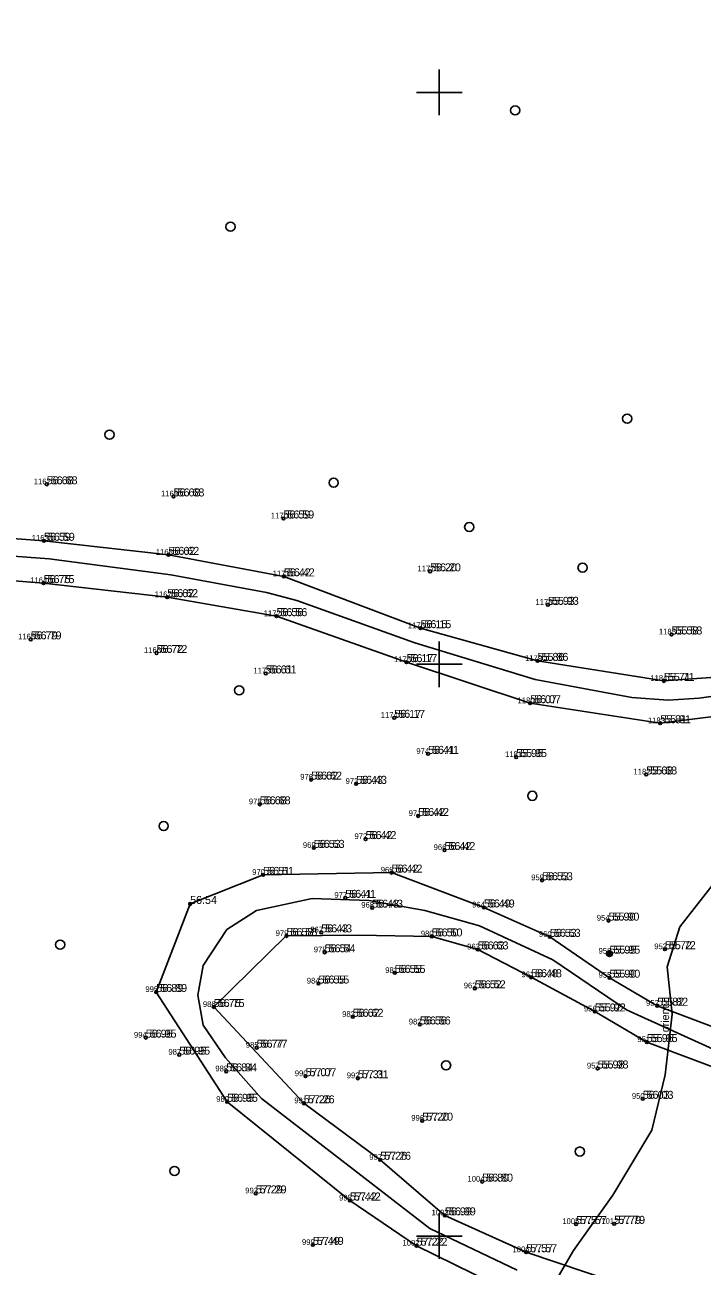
# Model space of a CAD drawing. Extents: x 554846 to 556995, y 6445875 to 6446723.
# Drawn here: x 555263.8 to 555323, y 6446097.4 to 6446205.9 of the extents above; entities that cross this region are included whole.
import ezdxf

# ---------------------------------------------------------------- set-up
doc = ezdxf.new("R2010")
doc.units = 0
for name, color, linetype in [('HALJASTUS', 7, 'Continuous'), ('KORGUS-EH2000', 7, 'Continuous'), ('MOOTKORG-EH2000', 7, 'Continuous'), ('MOOTMPUNKT', 7, 'Continuous'), ('MOOTNR', 7, 'Continuous'), ('RAJATIS', 7, 'Continuous'), ('SITRASS', 7, 'Continuous'), ('TEE', 7, 'Continuous'), ('VORK', 7, 'Continuous')]:
    doc.layers.add(name, color=color, linetype=linetype)

msp = doc.modelspace()

# ---------------------------------------------------------------- linework, layer by layer
at = {"layer": 'HALJASTUS'}
for centre in [(555306.63, 6446198.42), (555281.76, 6446188.25), (555316.42, 6446171.47), (555271.19, 6446170.07), (555290.78, 6446165.87), (555302.62, 6446161.99), (555312.52, 6446158.44), (555282.52, 6446147.72), (555308.14, 6446138.49), (555275.92, 6446135.85), (555266.88, 6446125.48), (555300.6, 6446114.93), (555312.28, 6446107.39), (555276.87, 6446105.69)]:
    msp.add_circle(centre, 0.4, dxfattribs=at)
at = {"layer": 'KORGUS-EH2000'}
for centre in [(555265.71, 6446165.73), (555276.79, 6446164.67), (555286.39, 6446162.74), (555265.47, 6446160.79), (555276.34, 6446159.56), (555286.43, 6446157.68), (555299.2, 6446158.12), (555265.44, 6446157.09), (555276.24, 6446155.86), (555309.5, 6446155.19), (555285.78, 6446154.2), (555298.36, 6446153.15), (555264.31, 6446152.17), (555320.29, 6446152.6), (555275.3, 6446150.98), (555297.14, 6446150.18), (555308.59, 6446150.29), (555284.84, 6446149.19), (555319.62, 6446148.54), (555307.94, 6446146.59), (555296.07, 6446145.31), (555319.3, 6446144.84), (555299.02, 6446142.16), (555306.72, 6446141.88), (555288.81, 6446139.91), (555318.09, 6446140.36), (555292.74, 6446139.54), (555284.32, 6446137.75), (555298.16, 6446136.73), (555293.57, 6446134.71), (555289.04, 6446133.94), (555300.46, 6446133.75), (555284.61, 6446131.58), (555295.84, 6446131.78), (555308.98, 6446131.11), (555291.79, 6446129.57), (555294.14, 6446128.71), (555303.9, 6446128.73), (555314.79, 6446127.58), (555286.66, 6446126.24), (555289.69, 6446126.55), (555299.34, 6446126.2), (555309.66, 6446126.16), (555289.99, 6446124.81), (555303.36, 6446125.06), (555319.72, 6446125.08), (555314.87, 6446124.69), (555296.11, 6446123.01), (555308.02, 6446122.63), (555314.87, 6446122.59), (555289.45, 6446122.08), (555303.11, 6446121.66), (555275.28, 6446121.34), (555280.3, 6446120.03), (555313.59, 6446119.64), (555319.05, 6446120.14), (555292.44, 6446119.17), (555298.31, 6446118.5), (555274.36, 6446117.35), (555284.05, 6446116.47), (555318.13, 6446116.96), (555277.29, 6446115.86), (555281.39, 6446114.4), (555288.32, 6446113.98), (555313.84, 6446114.65), (555292.89, 6446113.8), (555281.47, 6446111.74), (555317.78, 6446112), (555288.17, 6446111.61), (555298.51, 6446110.09), (555294.84, 6446106.67), (555303.75, 6446104.76), (555283.97, 6446103.73), (555292.2, 6446103.11), (555300.5, 6446101.81), (555311.95, 6446101.05), (555315.29, 6446101.07), (555288.96, 6446099.23), (555298.02, 6446099.16), (555307.6, 6446098.59)]:
    msp.add_circle(centre, 0.125, dxfattribs=at)
at = {"layer": 'MOOTMPUNKT'}
for centre in [(555265.71, 6446165.73), (555276.79, 6446164.67), (555286.39, 6446162.74), (555265.47, 6446160.79), (555276.34, 6446159.56), (555286.43, 6446157.68), (555299.2, 6446158.12), (555265.44, 6446157.09), (555276.24, 6446155.86), (555309.5, 6446155.19), (555285.78, 6446154.2), (555298.36, 6446153.15), (555264.31, 6446152.17), (555320.29, 6446152.6), (555275.3, 6446150.98), (555297.14, 6446150.18), (555308.59, 6446150.29), (555284.84, 6446149.19), (555319.62, 6446148.54), (555307.94, 6446146.59), (555296.07, 6446145.31), (555319.3, 6446144.84), (555299.02, 6446142.16), (555306.72, 6446141.88), (555288.81, 6446139.91), (555318.09, 6446140.36), (555292.74, 6446139.54), (555284.32, 6446137.75), (555298.16, 6446136.73), (555293.57, 6446134.71), (555289.04, 6446133.94), (555300.46, 6446133.75), (555284.61, 6446131.58), (555295.84, 6446131.78), (555308.98, 6446131.11), (555291.79, 6446129.57), (555278.24, 6446129.04), (555294.14, 6446128.71), (555303.9, 6446128.73), (555314.79, 6446127.58), (555286.66, 6446126.24), (555289.69, 6446126.55), (555299.34, 6446126.2), (555309.66, 6446126.16), (555289.99, 6446124.81), (555303.36, 6446125.06), (555319.72, 6446125.08), (555314.87, 6446124.69), (555296.11, 6446123.01), (555308.02, 6446122.63), (555314.87, 6446122.59), (555289.45, 6446122.08), (555303.11, 6446121.66), (555275.28, 6446121.34), (555280.3, 6446120.03), (555313.59, 6446119.64), (555319.05, 6446120.14), (555292.44, 6446119.17), (555298.31, 6446118.5), (555274.36, 6446117.35), (555284.05, 6446116.47), (555318.13, 6446116.96), (555277.29, 6446115.86), (555281.39, 6446114.4), (555288.32, 6446113.98), (555313.84, 6446114.65), (555292.89, 6446113.8), (555281.47, 6446111.74), (555317.78, 6446112), (555288.17, 6446111.61), (555298.51, 6446110.09), (555294.84, 6446106.67), (555303.75, 6446104.76), (555283.97, 6446103.73), (555292.2, 6446103.11), (555300.5, 6446101.81), (555311.95, 6446101.05), (555315.29, 6446101.07), (555288.96, 6446099.23), (555298.02, 6446099.16), (555307.6, 6446098.59)]:
    msp.add_circle(centre, 0.125, dxfattribs=at)
at = {"layer": 'RAJATIS'}
for radius in [0.25, 0.0234]:
    msp.add_circle((555314.87, 6446124.69), radius, dxfattribs=at)
at = {"layer": 'SITRASS'}
msp.add_lwpolyline([(555305.76, 6446088.51), (555311.73, 6446098.73), (555315.17, 6446103.59), (555318.56, 6446109.25), (555319.73, 6446114.11), (555320.34, 6446119.41), (555319.91, 6446123.53), (555321.02, 6446127.04), (555334.92, 6446144.83), (555339.43, 6446148.13), (555341.89, 6446149.32), (555360.14, 6446155.97), (555367.8, 6446158.19), (555388.11, 6446164.69), (555397.64, 6446165.99), (555410.43, 6446167.47), (555421.22, 6446169.41), (555430.68, 6446171.97), (555436.58, 6446173.1), (555447.3, 6446175.1), (555466.49, 6446179.22), (555474.82, 6446180.34)], dxfattribs=at)
at = {"layer": 'TEE'}
for points in [[(555247.52, 6446162.12), (555265.47, 6446160.79), (555276.34, 6446159.56), (555286.43, 6446157.68), (555298.36, 6446153.15), (555308.59, 6446150.29), (555319.62, 6446148.54), (555327.84, 6446149.13), (555331.85, 6446150.36), (555334.58, 6446153.35), (555334.79, 6446162.55), (555336.04, 6446172.56), (555338.65, 6446179.44), (555343.2, 6446186.87), (555348.65, 6446195.75), (555359.36, 6446208.2), (555362, 6446212.55), (555362.39, 6446223.83), (555370.17, 6446230.71), (555377.98, 6446233.66), (555385.78, 6446233.47)], [(555385.54, 6446229.68), (555377.59, 6446229.89), (555371.94, 6446227.34), (555367.7, 6446222.17), (555366.29, 6446212.41), (555362.23, 6446206.74), (555351.69, 6446194.25), (555346.07, 6446185.37), (555342.02, 6446178.62), (555340, 6446174.09), (555338.06, 6446163.9), (555338.78, 6446155.44), (555337.33, 6446148.82), (555334.66, 6446147.05), (555328.59, 6446146.01), (555319.3, 6446144.84), (555307.94, 6446146.59), (555297.14, 6446150.18), (555285.78, 6446154.2), (555276.24, 6446155.86), (555265.44, 6446157.09), (555246.52, 6446158.61)], [(555361.12, 6446207.96), (555350.96, 6446195.96), (555349.72, 6446194.5), (555348.27, 6446191.98), (555340.58, 6446179.38), (555338.43, 6446174.33), (555337.37, 6446169.52), (555336.62, 6446164.08), (555336.56, 6446160.5), (555336.73, 6446155.21), (555336.17, 6446151.94), (555334.85, 6446149.89), (555332.77, 6446148.62), (555329.39, 6446147.99), (555322.71, 6446147.02), (555320, 6446146.87), (555316.83, 6446147.08), (555308.37, 6446148.65), (555297.88, 6446151.87), (555287.56, 6446155.58), (555284.9, 6446156.28), (555276.56, 6446157.82), (555265.92, 6446159.2), (555247.57, 6446160.59)], [(555306.24, 6446095.09), (555298.02, 6446099.16), (555292.2, 6446103.11), (555281.47, 6446111.74), (555275.28, 6446121.34), (555278.24, 6446129.04), (555284.61, 6446131.58), (555295.84, 6446131.78), (555303.9, 6446128.73), (555309.66, 6446126.16), (555314.87, 6446122.59), (555319.05, 6446120.14), (555327.6, 6446116.89)], [(555306.81, 6446097.03), (555299.18, 6446100.65), (555292.5, 6446105.81), (555284.46, 6446112.02), (555281.34, 6446115.58), (555279.38, 6446118.44), (555278.91, 6446121.05), (555279.37, 6446123.66), (555281.44, 6446126.8), (555284.05, 6446128.47), (555288.9, 6446129.52), (555293.85, 6446129.35), (555298.74, 6446128.48), (555303.51, 6446127.13), (555309.92, 6446124.16), (555316.36, 6446119.78), (555323.93, 6446116.33)], [(555326.11, 6446113.96), (555318.13, 6446116.96), (555313.59, 6446119.64), (555308.02, 6446122.63), (555303.36, 6446125.06), (555299.34, 6446126.2), (555292.93, 6446126.32), (555286.64, 6446126.24), (555280.3, 6446120.03), (555288.17, 6446111.61), (555294.84, 6446106.67), (555300.5, 6446101.81), (555307.6, 6446098.59), (555315.46, 6446095.94)]]:
    msp.add_lwpolyline(points, dxfattribs=at)
at = {"layer": 'VORK'}
for p, q in [((555300, 6446202), (555300, 6446198)), ((555298, 6446200), (555302, 6446200)), ((555300, 6446152), (555300, 6446148)), ((555298, 6446150), (555302, 6446150)), ((555300, 6446102), (555300, 6446098)), ((555298, 6446100), (555302, 6446100))]:
    msp.add_line(p, q, dxfattribs=at)

# ---------------------------------------------------------------- texts
at = {"layer": 'KORGUS-EH2000'}
for s, p in [('56.68', (555266.06, 6446165.73)), ('56.68', (555277.14, 6446164.67)), ('56.59', (555286.73, 6446162.74)), ('56.59', (555265.82, 6446160.79)), ('56.62', (555276.69, 6446159.56)), ('56.20', (555299.55, 6446158.12)), ('56.75', (555265.79, 6446157.09)), ('56.42', (555286.78, 6446157.68)), ('56.62', (555276.59, 6446155.86)), ('55.93', (555309.85, 6446155.19)), ('56.56', (555286.13, 6446154.2)), ('56.15', (555298.71, 6446153.15)), ('55.58', (555320.64, 6446152.6)), ('56.79', (555264.66, 6446152.17)), ('56.72', (555275.65, 6446150.98)), ('56.17', (555297.49, 6446150.18)), ('55.86', (555308.94, 6446150.29)), ('56.61', (555285.19, 6446149.19)), ('55.71', (555319.97, 6446148.54)), ('56.07', (555308.29, 6446146.59)), ('56.17', (555296.42, 6446145.31)), ('55.81', (555319.65, 6446144.84)), ('56.41', (555299.37, 6446142.16)), ('55.95', (555307.07, 6446141.88)), ('56.62', (555289.16, 6446139.91)), ('56.43', (555293.09, 6446139.54)), ('55.68', (555318.44, 6446140.36)), ('56.68', (555284.67, 6446137.75)), ('56.42', (555298.51, 6446136.73)), ('56.53', (555289.39, 6446133.94)), ('56.42', (555293.92, 6446134.71)), ('56.42', (555300.81, 6446133.75)), ('56.42', (555296.19, 6446131.78)), ('56.51', (555284.96, 6446131.58)), ('56.53', (555309.33, 6446131.11)), ('56.41', (555292.14, 6446129.57)), ('56.43', (555294.49, 6446128.71)), ('56.49', (555304.25, 6446128.73)), ('55.90', (555315.14, 6446127.58)), ('56.43', (555290.04, 6446126.55)), ('56.58', (555287.01, 6446126.24)), ('56.50', (555299.69, 6446126.2)), ('56.53', (555310.01, 6446126.16)), ('56.54', (555290.34, 6446124.81)), ('56.63', (555303.71, 6446125.06)), ('55.95', (555315.22, 6446124.69)), ('55.72', (555320.07, 6446125.08)), ('56.55', (555289.8, 6446122.08)), ('56.55', (555296.46, 6446123.01)), ('56.48', (555308.37, 6446122.63)), ('55.90', (555315.22, 6446122.59)), ('56.89', (555275.63, 6446121.34)), ('56.52', (555303.46, 6446121.66)), ('56.75', (555280.65, 6446120.03)), ('55.82', (555319.4, 6446120.14)), ('56.62', (555292.79, 6446119.17)), ('55.92', (555313.94, 6446119.64)), ('56.56', (555298.66, 6446118.5)), ('56.95', (555274.71, 6446117.35)), ('55.95', (555318.48, 6446116.96)), ('56.95', (555277.64, 6446115.86)), ('56.77', (555284.4, 6446116.47)), ('56.84', (555281.73, 6446114.4)), ('55.98', (555314.19, 6446114.65)), ('57.07', (555288.67, 6446113.98)), ('57.31', (555293.24, 6446113.8)), ('56.95', (555281.82, 6446111.74)), ('57.26', (555288.52, 6446111.61)), ('56.03', (555318.12, 6446112)), ('57.20', (555298.86, 6446110.09)), ('57.26', (555295.19, 6446106.67)), ('56.80', (555304.1, 6446104.76)), ('57.29', (555284.32, 6446103.73)), ('57.42', (555292.55, 6446103.11)), ('56.99', (555300.85, 6446101.81)), ('57.57', (555312.3, 6446101.05)), ('57.79', (555315.64, 6446101.07)), ('57.49', (555289.31, 6446099.23)), ('57.22', (555298.37, 6446099.16)), ('57.57', (555307.95, 6446098.59))]:
    msp.add_text(s, height=0.7, dxfattribs=at).set_placement(p)
at = {"layer": 'MOOTKORG-EH2000'}
for s, p in [('56.68', (555265.71, 6446165.73)), ('56.68', (555276.79, 6446164.67)), ('56.59', (555286.39, 6446162.74)), ('56.59', (555265.47, 6446160.79)), ('56.62', (555276.34, 6446159.56)), ('56.20', (555299.2, 6446158.12)), ('56.75', (555265.44, 6446157.09)), ('56.42', (555286.43, 6446157.68)), ('56.62', (555276.24, 6446155.86)), ('55.93', (555309.5, 6446155.19)), ('56.56', (555285.78, 6446154.2)), ('56.15', (555298.36, 6446153.15)), ('55.58', (555320.29, 6446152.6)), ('56.79', (555264.31, 6446152.17)), ('56.72', (555275.3, 6446150.98)), ('56.17', (555297.14, 6446150.18)), ('55.86', (555308.59, 6446150.29)), ('56.61', (555284.84, 6446149.19)), ('55.71', (555319.62, 6446148.54)), ('56.07', (555307.94, 6446146.59)), ('56.17', (555296.07, 6446145.31)), ('55.81', (555319.3, 6446144.84)), ('56.41', (555299.02, 6446142.16)), ('55.95', (555306.72, 6446141.88)), ('56.62', (555288.81, 6446139.91)), ('56.43', (555292.74, 6446139.54)), ('55.68', (555318.09, 6446140.36)), ('56.68', (555284.32, 6446137.75)), ('56.42', (555298.16, 6446136.73)), ('56.53', (555289.04, 6446133.94)), ('56.42', (555293.57, 6446134.71)), ('56.42', (555300.46, 6446133.75)), ('56.42', (555295.84, 6446131.78)), ('56.51', (555284.61, 6446131.58)), ('56.53', (555308.98, 6446131.11)), ('56.41', (555291.79, 6446129.57)), ('56.54', (555278.24, 6446129.04)), ('56.43', (555294.14, 6446128.71)), ('56.49', (555303.9, 6446128.73)), ('55.90', (555314.79, 6446127.58)), ('56.43', (555289.69, 6446126.55)), ('56.58', (555286.66, 6446126.24)), ('56.50', (555299.34, 6446126.2)), ('56.53', (555309.66, 6446126.16)), ('56.54', (555289.99, 6446124.81)), ('56.63', (555303.36, 6446125.06)), ('55.95', (555314.87, 6446124.69)), ('55.72', (555319.72, 6446125.08)), ('56.55', (555289.45, 6446122.08)), ('56.55', (555296.11, 6446123.01)), ('56.48', (555308.02, 6446122.63)), ('55.90', (555314.87, 6446122.59)), ('56.89', (555275.28, 6446121.34)), ('56.52', (555303.11, 6446121.66)), ('56.75', (555280.3, 6446120.03)), ('55.82', (555319.05, 6446120.14)), ('56.62', (555292.44, 6446119.17)), ('55.92', (555313.59, 6446119.64)), ('56.56', (555298.31, 6446118.5)), ('56.95', (555274.36, 6446117.35)), ('55.95', (555318.13, 6446116.96)), ('56.95', (555277.29, 6446115.86)), ('56.77', (555284.05, 6446116.47)), ('56.84', (555281.39, 6446114.4)), ('55.98', (555313.84, 6446114.65)), ('57.07', (555288.32, 6446113.98)), ('57.31', (555292.89, 6446113.8)), ('56.95', (555281.47, 6446111.74)), ('57.26', (555288.17, 6446111.61)), ('56.03', (555317.78, 6446112)), ('57.20', (555298.51, 6446110.09)), ('57.26', (555294.84, 6446106.67)), ('56.80', (555303.75, 6446104.76)), ('57.29', (555283.97, 6446103.73)), ('57.42', (555292.2, 6446103.11)), ('56.99', (555300.5, 6446101.81)), ('57.57', (555311.95, 6446101.05)), ('57.79', (555315.29, 6446101.07)), ('57.49', (555288.96, 6446099.23)), ('57.22', (555298.02, 6446099.16)), ('57.57', (555307.6, 6446098.59))]:
    msp.add_text(s, height=0.7, dxfattribs=at).set_placement(p)
at = {"layer": 'MOOTNR'}
for s, p in [('1162', (555264.58, 6446165.73)), ('1169', (555275.69, 6446164.67)), ('1170', (555285.29, 6446162.74)), ('1163', (555264.4, 6446160.79)), ('1168', (555275.24, 6446159.56)), ('1177', (555298.1, 6446158.12)), ('1164', (555264.27, 6446157.09)), ('1171', (555285.45, 6446157.68)), ('1167', (555275.14, 6446155.86)), ('1178', (555308.4, 6446155.19)), ('1172', (555284.66, 6446154.2)), ('1176', (555297.26, 6446153.15)), ('1185', (555319.19, 6446152.6)), ('1165', (555263.21, 6446152.17)), ('1166', (555274.2, 6446150.98)), ('1175', (555296.04, 6446150.18)), ('1179', (555307.49, 6446150.29)), ('1173', (555283.77, 6446149.19)), ('1184', (555318.44, 6446148.54)), ('1180', (555306.84, 6446146.59)), ('1174', (555294.89, 6446145.31)), ('1183', (555318.23, 6446144.84)), ('974', (555298, 6446142.16)), ('1181', (555305.75, 6446141.88)), ('976', (555287.86, 6446139.91)), ('973', (555291.82, 6446139.54)), ('1182', (555316.97, 6446140.36)), ('975', (555283.37, 6446137.75)), ('971', (555297.33, 6446136.73)), ('972', (555292.59, 6446134.71)), ('969', (555288.09, 6446133.94)), ('966', (555299.51, 6446133.75)), ('970', (555283.66, 6446131.58)), ('965', (555294.89, 6446131.78)), ('959', (555308.03, 6446131.11)), ('977', (555290.84, 6446129.57)), ('968', (555293.19, 6446128.71)), ('964', (555302.87, 6446128.73)), ('954', (555313.76, 6446127.58)), ('967', (555288.74, 6446126.55)), ('979', (555285.71, 6446126.24)), ('980', (555298.39, 6446126.2)), ('960', (555308.71, 6446126.16)), ('978', (555289.04, 6446124.81)), ('963', (555302.44, 6446125.06)), ('958', (555313.92, 6446124.69)), ('953', (555318.79, 6446125.08)), ('981', (555295.28, 6446123.01)), ('961', (555307.19, 6446122.63)), ('955', (555313.92, 6446122.59)), ('995', (555274.33, 6446121.34)), ('984', (555288.43, 6446122.08)), ('962', (555302.14, 6446121.66)), ('986', (555279.35, 6446120.03)), ('952', (555318.07, 6446120.14)), ('983', (555291.52, 6446119.17)), ('956', (555312.64, 6446119.64)), ('982', (555297.34, 6446118.5)), ('994', (555273.33, 6446117.35)), ('951', (555317.31, 6446116.96)), ('987', (555276.34, 6446115.86)), ('985', (555283.1, 6446116.47)), ('957', (555312.9, 6446114.65)), ('988', (555280.44, 6446114.4)), ('990', (555287.38, 6446113.98)), ('992', (555291.92, 6446113.8)), ('989', (555280.52, 6446111.74)), ('991', (555287.34, 6446111.61)), ('950', (555316.83, 6446112)), ('996', (555297.56, 6446110.09)), ('997', (555293.89, 6446106.67)), ('993', (555283.05, 6446103.73)), ('1004', (555302.47, 6446104.76)), ('998', (555291.25, 6446103.11)), ('1003', (555299.33, 6446101.81)), ('1005', (555310.75, 6446101.05)), ('1012', (555314.16, 6446101.07)), ('999', (555288.01, 6446099.23)), ('1002', (555296.79, 6446099.16)), ('1006', (555306.4, 6446098.59))]:
    msp.add_text(s, height=0.5, dxfattribs=at).set_placement(p)
at = {"layer": 'SITRASS'}
msp.add_text('orient', height=0.7, rotation=90.433, dxfattribs=at).set_placement((555320.09, 6446117.82))

doc.saveas('drawing.dxf')
